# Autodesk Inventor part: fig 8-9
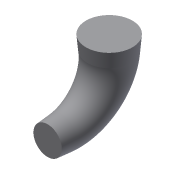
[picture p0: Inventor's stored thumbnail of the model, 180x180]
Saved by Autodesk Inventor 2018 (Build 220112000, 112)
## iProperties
Shininess: 77.0
Length Units: 11269
Angle Units: 11279
Time Units: 11290
Mass Units: 11283
Length Display Precision: 3
Angle Display Precision: 2
Created: 2001-12
Part Number: fig 8-9
Document SubType Name: Modeling
Designer: CADSoft
Density: 1 g/cm^3
Material: Generic
Appearance: Default
Density: 0.0
Volumn: 0.0
Area: 0.0
PropertySet Name: Model Information
Control State: 0
Master: False
Checked Out: False
Author: CADSoft
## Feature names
1. Sweep7
## Parameters: d4 = 15 mm, d5 = 15 mm, d13 = 5 deg, d14 = 0
